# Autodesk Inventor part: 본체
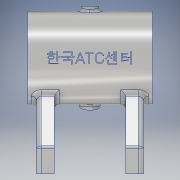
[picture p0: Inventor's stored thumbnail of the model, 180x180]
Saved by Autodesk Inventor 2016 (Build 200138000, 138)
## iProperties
Created: 2018-05
Part Number: 본체
Material: 알루미늄 6061
Document SubType Name: Modeling
Designer: USER
Mass: 318.264 g
Surface Area: 376.74 cm^2
Volume: 117.875 cm^3
Density: 2.7 g/cm^3
Appearance: 알루미늄 - 평지
Author: USER
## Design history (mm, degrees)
sketch "스케치1"
  geometry: L1 (-35, 0)-(35, 0); L2 (-35, 16)-(-35, 26); L3 (-35, 26)-(35, 26); L4 (35, 26)-(35, 16); L5 (35, 16)-(23, 16); L6 (23, 16)-(23, 14); L7 (23, 14)-(21, 14); L8 (21, 14)-(21, 21); L9 (21, 21)-(-21, 21); L10 (-21, 21)-(-21, 14); L11 (-21, 14)-(-23, 14); L12 (-23, 14)-(-23, 16); L13 (-23, 16)-(-35, 16); 2 further points
  constraints: 26 end point, 10 perpendicular, 2 point on line, 2 vertical alignment, 1 coincident, 1 horizontal, 1 midpoint, 1 vertical
  dimensions: "d0" = 70 distance of L1.start L1.end; "d1" = 42 diameter of L9 L1; "d2" = 52 diameter of L3 L1; "d3" = 32 diameter of L13 L1; "d4" = 28 diameter of L11 L1; "d6" = 42 distance of L8.end L9.end; "d7" = 2 distance of L10.end L11.end; "d8" = 2 distance of L6.end L7.end; "d9" = 12 distance of L12.end L2.start; "d74" = 32 diameter of L5 L1
revolve "회전1" sketch "스케치1" stored, may be unused: angle "d10" = 90 deg
node "작업 평면2"
  node "작업 평면1"
sketch "스케치2"
  geometry: L1 (0, 0)-(-65, 0); L2 (-65, 35)-(-65, -35); L3 (-65, 35)-(-50, 35); L4 (-50, 35)-(-19.386, 17.325); L5 (-50, 35)-(-3.646, 35); L6 (-50, -35)-(-19.386, -17.325); L7 (-65, -35)-(-50, -35); A1 r 26 centre (0, 0) between (-19.386, 17.325) and (-19.386, -17.325); 1 further point
  constraints: 14 end point, 4 horizontal, 2 point on circle, 2 symmetric about line, 1 centre point, 1 coincident, 1 midpoint, 1 vertical, 2 other
  dimensions: "d12" = 65 distance of L1.end L1.start; "d13" = 70 distance of L2.start L2.end; "d14" = 15 distance of L2.start L3.end; "d15" = 30 deg angle of L4 L5
extrude "돌출1" join sketch "스케치2" distance "d16" = 10; taper "d17" = 0 deg
sketch "스케치3"
  geometry: L1 (0, 0)-(10, 0) reference; L2 (10, 70)-(10, 0) reference; L3 (0, 70)-(10, 70) reference; L4 (10, 17.675)-(10, 52.325) reference; L5 (10, 35)-(0, 35); L6 (0, 70)-(0, 0) reference; 3 further points
  constraints: 2 end point, 1 midpoint, 1 symmetric about line
  dimensions: "d18" = 20 distance from line of point (5, 15) L5
hole "구멍1" sketch "스케치3" at (5, 15), (5, 55) diameter "d19" = 4.134; stored, may be unused: countersink angle "d23" = 90 deg, drill point angle "d25" = 118 deg; dims "d20" = 8, "d21" = 4, "d22" = 2, "d24" = 10
sketch "스케치4"
  geometry: C1 r 21 at (0, 0); 2 further points
  constraints: 1 centre point, 1 coincident
  dimensions: "d26" = 42 diameter of C1; "d27" = 21 distance of point (0, 0) point (-21, 0)
hole "구멍2" sketch "스케치4" at (-21, 0) diameter "d28" = 3.242; stored, may be unused: countersink angle "d32" = 90 deg, drill point angle "d34" = 118 deg; dims "d29" = 8, "d30" = 4, "d31" = 2, "d33" = 10
node "작업 평면5"
sketch "스케치7"
  geometry: L1 (0, 0)-(-50.719, 0); L2 (0, 0)-(-27.251, -9.919)
  constraints: 4 end point, 1 horizontal
  dimensions: "d49" = 20 deg angle of L2 L1; "d50" = 29 distance of L1.start L2.end
node "작업 평면6"
sketch "스케치8"
  geometry: C1 r 6 at (0, 0); 1 further point
  constraints: 1 centre point, 1 coincident
  dimensions: "d51" = 12 diameter of C1
extrude "돌출3" join sketch "스케치8" stored distance "d52" = 10; taper "d53" = 0 deg
sketch "스케치9"
  geometry: 1 further point
hole "구멍4" sketch "스케치9" at (0, 0) diameter "d54" = 4.917; stored, may be unused: countersink angle "d58" = 90 deg, drill point angle "d60" = 118 deg; dims "d55" = 30, "d56" = 4, "d57" = 2, "d59" = 35
fillet "모깎기1" dims "d61" = 0.3
fillet "모깎기2" dims "d62" = 3
fillet "모깎기3" dims "d63" = 2
chamfer "모따기1" distance "d64" = 1; stored, may be unused: second distance "d65" = 2, angle "d66" = 45 deg
fillet "모깎기4" dims "d67" = 3
fillet "모깎기5" dims "d68" = 3
node "작업 평면7"
sketch "스케치10"
  geometry: L1 (-35, 26)-(-35, -26) reference; 2 further points
  constraints: 1 other
  dimensions: "d70" = 35 distance from line of L1 point (0, 0); "d71" = 26 vertical distance of L1.start point (0, 0)
feature "엠보싱1" sketch "스케치10" dims "d0" = 70, "d1" = 42, "d2" = 52, "d3" = 32, "d4" = 28, "d6" = 42, "d7" = 2, "d8" = 2, "d9" = 12, "d72" = 0.5, "d73" = 0, "d74" = 32
node "작업 평면9"
  node "작업 평면8"
sketch "스케치13"
  geometry: C1 r 5 at (0, 0); 1 further point
  constraints: 1 centre point, 1 coincident
  dimensions: "d77" = 10 diameter of C1
extrude "돌출4" join sketch "스케치13" stored distance "d78" = 10; taper "d79" = 0 deg
sketch "스케치14"
  geometry: 1 further point
hole "구멍5" sketch "스케치14" at (0, 0) diameter "d80" = 5.188; stored, may be unused: countersink angle "d84" = 90 deg, drill point angle "d86" = 118 deg; dims "d81" = 35, "d82" = 4, "d83" = 2, "d85" = 35
fillet "모깎기6" dims "d87" = 2
node "솔리드1"
mirror "대칭1"
pattern_circular "원형 패턴1" dims angle "d36" = 360 deg
mirror "대칭2"
node "투영된 루프1"
other parameters: "d69" = 61.5, "d75" = 26, "d76" = 3
